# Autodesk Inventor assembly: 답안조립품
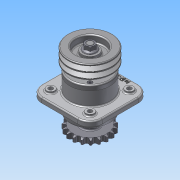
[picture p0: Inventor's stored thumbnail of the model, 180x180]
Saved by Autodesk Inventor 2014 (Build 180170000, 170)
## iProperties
Created: 2015-09
Part Number: 답안조립품
Document SubType Name: Assembly
Designer: study
Author: study
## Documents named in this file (12)
- C:\Users\study\Desktop\450909V1007\답안조립품.iam
- C:\Users\study\Desktop\450909V1007\1-본체.ipt
- C:\Users\study\Desktop\450909V1007\3-축.ipt
- C:\Users\study\Desktop\450909V1007\6-베어링 6206.ipt
- C:\Users\study\Desktop\450909V1007\2-커버.ipt
- C:\Users\study\Desktop\450909V1007\11-키 6x6.ipt
- C:\Users\study\Desktop\450909V1007\4-V벨트풀리.ipt
- C:\Users\study\Desktop\450909V1007\5-체인 스프로킷.ipt
- C:\Users\study\Desktop\450909V1007\7-부시.ipt
- C:\Users\study\Desktop\450909V1007\8-오일실 30x42.ipt
- C:\Users\study\Desktop\450909V1007\9-M16-너트.ipt
- C:\Users\study\Desktop\450909V1007\10-M6.ipt
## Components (23 placed, 11 different names)
1. 1-본체:1
2. 3-축:1 — 각도:1, 각도:2
3. 6-베어링 6206:1
4. 6-베어링 6206:2
5. 2-커버:1
6. 2-커버:2
7. 11-키 6x6:1 — 각도:2, 각도:3
8. 11-키 6x6:2 — 각도:1, 각도:4
9. 4-V벨트풀리:1 — 각도:4, 각도:5
10. 5-체인 스프로킷:1 — 각도:3, 각도:6
11. 7-부시:1
12. 8-8-오일실 30x42:1
13. 8-8-오일실 30x42:2
14. 9-M16 너트:1 — 각도:6
15. 9-M16 너트:2 — 각도:5
16. 10-M6:2
17. 10-M6:3
18. 10-M6:4
19. 10-M6:5
20. 10-M6:1
21. 10-M6:6
22. 10-M6:7
23. 10-M6:8
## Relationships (6: Angle 6)
- 각도:1 [Angle]: 3-축:1 ↔ 11-키 6x6:2
- 각도:2 [Angle]: 3-축:1 ↔ 11-키 6x6:1
- 각도:3 [Angle]: 11-키 6x6:1 ↔ 5-체인 스프로킷:1
- 각도:4 [Angle]: 11-키 6x6:2 ↔ 4-V벨트풀리:1
- 각도:5 [Angle]: 4-V벨트풀리:1 ↔ 9-M16 너트:2
- 각도:6 [Angle]: 5-체인 스프로킷:1 ↔ 9-M16 너트:1
